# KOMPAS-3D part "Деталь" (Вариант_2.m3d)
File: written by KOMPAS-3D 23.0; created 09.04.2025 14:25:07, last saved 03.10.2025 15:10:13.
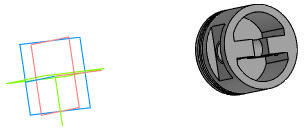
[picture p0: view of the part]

Document properties: Автор: Admin; Полное имя файла: C:\Users\ssafo\OneDrive\Desktop\ЦД_Грант\Решенные варианты\Вариант_2.m3d

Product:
- Part/product: Деталь
    Масса: 0.390577

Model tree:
1. Эскиз:1
2. Элемент вращения:1
     Угол 1 = 360
3. Эскиз:2
4. Эскиз:9  (with: Элемент вращения:1)
5. Элемент выдавливания:12
     Расстояние 1 = 30; Расстояние 2 = 30
6. Эскиз:10  (with: Элемент выдавливания:12, Элемент вращения:1)
7. Элемент выдавливания:15
     Расстояние 2 = 53
8. Эскиз:11  (with: Элемент вращения:1)
9. Элемент выдавливания:17
     Расстояние 2 = 29
10. Фаска:1  (with: Элемент выдавливания:15)
     Угол = 30; Длина 1 = 1; Длина 2 = 0.57735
